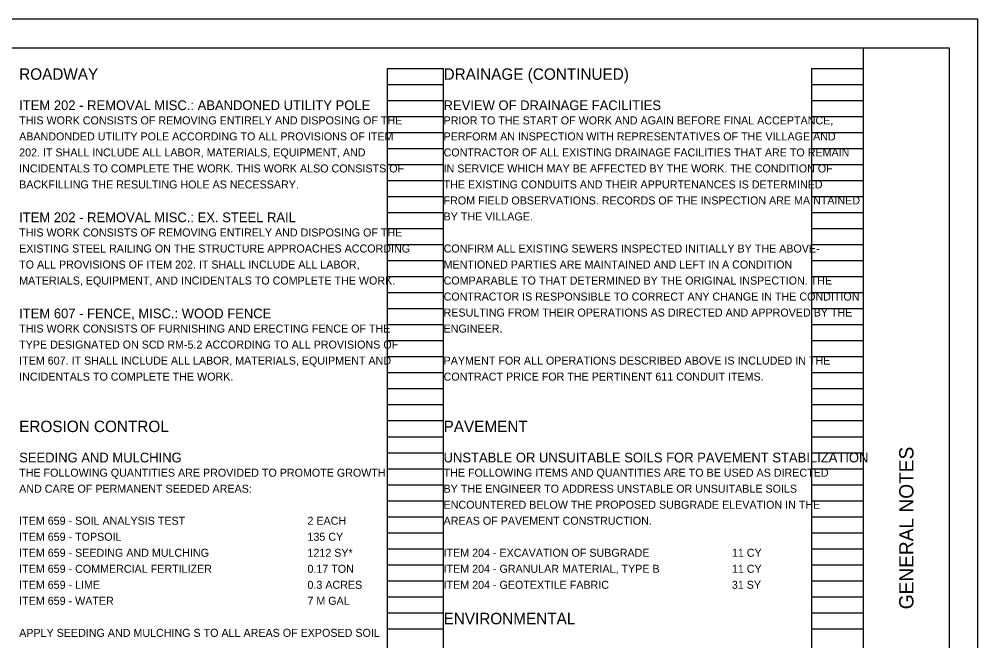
# Model space of a CAD drawing. Extents: x 0 to 34, y 0 to 22.
# Drawn here: x 17.24 to 34, y 11.13 to 22 of the extents above; entities that cross this region are included whole.
import ezdxf

# ---------------------------------------------------------------- set-up
doc = ezdxf.new("R2010")
doc.units = 0
for name, color, linetype in [('SH_Border', 7, 'Continuous'), ('SH_Cut_Line', 7, 'Continuous'), ('SH_Data', 7, 'Continuous'), ('SH_Text', 7, 'Continuous')]:
    doc.layers.add(name, color=color, linetype=linetype)

msp = doc.modelspace()

# ---------------------------------------------------------------- linework, layer by layer
at = {"layer": 'SH_Border'}
msp.add_line((32, 0.5), (32, 21.5), dxfattribs=at)
msp.add_lwpolyline([(1.5, 21.5), (33.5, 21.5), (33.5, 0.5), (1.5, 0.5)], close=True, dxfattribs=at)
at = {"layer": 'SH_Cut_Line'}
msp.add_lwpolyline([(0, 0), (34, 0), (34, 22), (0, 22)], close=True, dxfattribs=at)
at = {"layer": 'SH_Data'}
for p, q in [((23.68, 0.98), (23.68, 21.14)), ((23.68, 21.14), (24.66, 21.14)), ((24.66, 0.98), (24.66, 21.14)), ((31.1, 0.98), (31.1, 21.14)), ((31.1, 21.14), (32, 21.14)), ((32, 0.98), (32, 21.14)), ((23.68, 20.86), (24.66, 20.86)), ((31.1, 20.86), (32, 20.86)), ((23.68, 20.58), (24.66, 20.58)), ((31.1, 20.58), (32, 20.58)), ((23.68, 20.3), (24.66, 20.3)), ((31.1, 20.3), (32, 20.3)), ((23.68, 20.02), (24.66, 20.02)), ((31.1, 20.02), (32, 20.02)), ((23.68, 19.74), (24.66, 19.74)), ((31.1, 19.74), (32, 19.74)), ((23.68, 19.46), (24.66, 19.46)), ((31.1, 19.46), (32, 19.46)), ((23.68, 19.18), (24.66, 19.18)), ((31.1, 19.18), (32, 19.18)), ((23.68, 18.9), (24.66, 18.9)), ((31.1, 18.9), (32, 18.9)), ((23.68, 18.62), (24.66, 18.62)), ((31.1, 18.62), (32, 18.62)), ((23.68, 18.34), (24.66, 18.34)), ((31.1, 18.34), (32, 18.34)), ((23.68, 18.06), (24.66, 18.06)), ((31.1, 18.06), (32, 18.06)), ((23.68, 17.78), (24.66, 17.78)), ((31.1, 17.78), (32, 17.78)), ((23.68, 17.5), (24.66, 17.5)), ((31.1, 17.5), (32, 17.5)), ((23.68, 17.22), (24.66, 17.22)), ((31.1, 17.22), (32, 17.22)), ((23.68, 16.94), (24.66, 16.94)), ((31.1, 16.94), (32, 16.94)), ((23.68, 16.66), (24.66, 16.66)), ((31.1, 16.66), (32, 16.66)), ((23.68, 16.38), (24.66, 16.38)), ((31.1, 16.38), (32, 16.38)), ((23.68, 16.1), (24.66, 16.1)), ((31.1, 16.1), (32, 16.1)), ((23.68, 15.82), (24.66, 15.82)), ((31.1, 15.82), (32, 15.82)), ((23.68, 15.54), (24.66, 15.54)), ((31.1, 15.54), (32, 15.54)), ((23.68, 15.26), (24.66, 15.26)), ((31.1, 15.26), (32, 15.26)), ((23.68, 14.98), (24.66, 14.98)), ((31.1, 14.98), (32, 14.98)), ((23.68, 14.7), (24.66, 14.7)), ((31.1, 14.7), (32, 14.7)), ((23.68, 14.42), (24.66, 14.42)), ((31.1, 14.42), (32, 14.42)), ((23.68, 14.14), (24.66, 14.14)), ((31.1, 14.14), (32, 14.14)), ((23.68, 13.86), (24.66, 13.86)), ((31.1, 13.86), (32, 13.86)), ((23.68, 13.58), (24.66, 13.58)), ((31.1, 13.58), (32, 13.58)), ((23.68, 13.3), (24.66, 13.3)), ((31.1, 13.3), (32, 13.3)), ((23.68, 13.02), (24.66, 13.02)), ((31.1, 13.02), (32, 13.02)), ((23.68, 12.74), (24.66, 12.74)), ((31.1, 12.74), (32, 12.74)), ((23.68, 12.46), (24.66, 12.46)), ((31.1, 12.46), (32, 12.46)), ((23.68, 12.18), (24.66, 12.18)), ((31.1, 12.18), (32, 12.18)), ((23.68, 11.9), (24.66, 11.9)), ((31.1, 11.9), (32, 11.9)), ((23.68, 11.62), (24.66, 11.62)), ((31.1, 11.62), (32, 11.62)), ((23.68, 11.34), (24.66, 11.34)), ((31.1, 11.34), (32, 11.34))]:
    msp.add_line(p, q, dxfattribs=at)

# ---------------------------------------------------------------- texts
msp.add_text('GENERAL NOTES', height=0.25, rotation=90, dxfattribs=at).set_placement((32.875, 11.682))
at = {"layer": 'SH_Text'}
for s, height, p in [('ROADWAY', 0.2, (17.24, 20.94)), ('DRAINAGE (CONTINUED)', 0.2, (24.66, 20.94)), ('ITEM 202 - REMOVAL MISC.: ABANDONED UTILITY POLE', 0.17, (17.24, 20.41)), ('REVIEW OF DRAINAGE FACILITIES', 0.17, (24.66, 20.41)), ('THIS WORK CONSISTS OF REMOVING ENTIRELY AND DISPOSING OF THE ', 0.14, (17.24, 20.16)), ('PRIOR TO THE START OF WORK AND AGAIN BEFORE FINAL ACCEPTANCE,', 0.14, (24.66, 20.16)), ('ABANDONDED UTILITY POLE ACCORDING TO ALL PROVISIONS OF ITEM ', 0.14, (17.24, 19.88)), ('PERFORM AN INSPECTION WITH REPRESENTATIVES OF THE VILLAGE AND', 0.14, (24.66, 19.88)), ('202. IT SHALL INCLUDE ALL LABOR, MATERIALS, EQUIPMENT, AND ', 0.14, (17.24, 19.6)), ('CONTRACTOR OF ALL EXISTING DRAINAGE FACILITIES THAT ARE TO REMAIN', 0.14, (24.66, 19.6)), ('INCIDENTALS TO COMPLETE THE WORK. THIS WORK ALSO CONSISTS OF ', 0.14, (17.24, 19.32)), ('IN SERVICE WHICH MAY BE AFFECTED BY THE WORK. THE CONDITION OF', 0.14, (24.66, 19.32)), ('BACKFILLING THE RESULTING HOLE AS NECESSARY.', 0.14, (17.24, 19.04)), ('THE EXISTING CONDUITS AND THEIR APPURTENANCES IS DETERMINED', 0.14, (24.66, 19.04)), ('FROM FIELD OBSERVATIONS. RECORDS OF THE INSPECTION ARE MAINTAINED', 0.14, (24.66, 18.76)), ('ITEM 202 - REMOVAL MISC.: EX. STEEL RAIL', 0.17, (17.24, 18.45)), ('BY THE VILLAGE.', 0.14, (24.66, 18.48)), ('THIS WORK CONSISTS OF REMOVING ENTIRELY AND DISPOSING OF THE ', 0.14, (17.24, 18.2)), ('EXISTING STEEL RAILING ON THE STRUCTURE APPROACHES ACCORDING ', 0.14, (17.24, 17.92)), ('CONFIRM ALL EXISTING SEWERS INSPECTED INITIALLY BY THE ABOVE-', 0.14, (24.66, 17.92)), ('TO ALL PROVISIONS OF ITEM 202. IT SHALL INCLUDE ALL LABOR, ', 0.14, (17.24, 17.64)), ('MENTIONED PARTIES ARE MAINTAINED AND LEFT IN A CONDITION', 0.14, (24.66, 17.64)), ('MATERIALS, EQUIPMENT, AND INCIDENTALS TO COMPLETE THE WORK.', 0.14, (17.24, 17.36)), ('COMPARABLE TO THAT DETERMINED BY THE ORIGINAL INSPECTION. THE', 0.14, (24.66, 17.36)), ('CONTRACTOR IS RESPONSIBLE TO CORRECT ANY CHANGE IN THE CONDITION', 0.14, (24.66, 17.08)), ('ITEM 607 - FENCE, MISC.: WOOD FENCE', 0.17, (17.24, 16.77)), ('RESULTING FROM THEIR OPERATIONS AS DIRECTED AND APPROVED BY THE', 0.14, (24.66, 16.8)), ('THIS WORK CONSISTS OF FURNISHING AND ERECTING FENCE OF THE ', 0.14, (17.24, 16.52)), ('ENGINEER.', 0.14, (24.66, 16.52)), ('TYPE DESIGNATED ON SCD RM-5.2 ACCORDING TO ALL PROVISIONS OF ', 0.14, (17.24, 16.24)), ('ITEM 607. IT SHALL INCLUDE ALL LABOR, MATERIALS, EQUIPMENT AND ', 0.14, (17.24, 15.96)), ('PAYMENT FOR ALL OPERATIONS DESCRIBED ABOVE IS INCLUDED IN THE', 0.14, (24.66, 15.96)), ('INCIDENTALS TO COMPLETE THE WORK.', 0.14, (17.24, 15.68)), ('CONTRACT PRICE FOR THE PERTINENT 611 CONDUIT ITEMS.', 0.14, (24.66, 15.68)), ('EROSION CONTROL', 0.2, (17.24, 14.78)), ('PAVEMENT', 0.2, (24.66, 14.78)), ('SEEDING AND MULCHING', 0.17, (17.24, 14.25)), ('UNSTABLE OR UNSUITABLE SOILS FOR PAVEMENT STABILIZATION', 0.17, (24.66, 14.25)), ('THE FOLLOWING QUANTITIES ARE PROVIDED TO PROMOTE GROWTH ', 0.14, (17.24, 14)), ('THE FOLLOWING ITEMS AND QUANTITIES ARE TO BE USED AS DIRECTED ', 0.14, (24.66, 14)), ('AND CARE OF PERMANENT SEEDED AREAS:', 0.14, (17.24, 13.72)), ('BY THE ENGINEER TO ADDRESS UNSTABLE OR UNSUITABLE SOILS ', 0.14, (24.66, 13.72)), ('ENCOUNTERED BELOW THE PROPOSED SUBGRADE ELEVATION IN THE ', 0.14, (24.66, 13.44)), ('ITEM 659 - SOIL ANALYSIS TEST', 0.14, (17.24, 13.16)), ('2 EACH', 0.14, (22.28, 13.16)), ('AREAS OF PAVEMENT CONSTRUCTION.', 0.14, (24.66, 13.16)), ('ITEM 659 - TOPSOIL', 0.14, (17.24, 12.88)), ('135 CY', 0.14, (22.28, 12.88)), ('ITEM 659 - SEEDING AND MULCHING', 0.14, (17.24, 12.6)), ('1212 SY*', 0.14, (22.28, 12.6)), ('ITEM 204 - EXCAVATION OF SUBGRADE', 0.14, (24.66, 12.6)), ('11 CY', 0.14, (29.7, 12.6)), ('ITEM 659 - COMMERCIAL FERTILIZER', 0.14, (17.24, 12.32)), ('0.17 TON', 0.14, (22.28, 12.32)), ('ITEM 204 - GRANULAR MATERIAL, TYPE B', 0.14, (24.66, 12.32)), ('11 CY', 0.14, (29.7, 12.32)), ('ITEM 659 - LIME', 0.14, (17.24, 12.04)), ('0.3 ACRES', 0.14, (22.28, 12.04)), ('ITEM 204 - GEOTEXTILE FABRIC', 0.14, (24.66, 12.04)), ('31 SY', 0.14, (29.7, 12.04)), ('ITEM 659 - WATER', 0.14, (17.24, 11.76)), ('7 M GAL', 0.14, (22.28, 11.76)), ('ENVIRONMENTAL', 0.2, (24.66, 11.42)), ('APPLY SEEDING AND MULCHING S TO ALL AREAS OF EXPOSED SOIL ', 0.14, (17.24, 11.2))]:
    msp.add_text(s, height=height, dxfattribs=at).set_placement(p)

doc.saveas('drawing.dxf')
